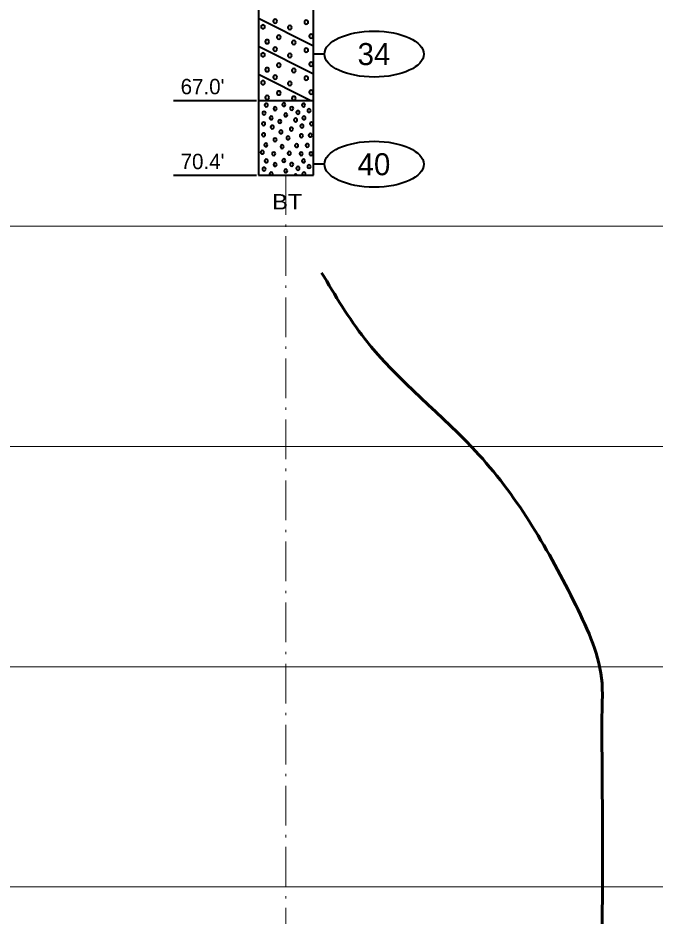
# Model space of a CAD drawing. Extents: x -76 to 974, y -1080 to -735.
# Drawn here: x 746.57 to 775.52, y -1033.41 to -992.64 of the extents above; entities that cross this region are included whole.
import ezdxf
from ezdxf.enums import TextEntityAlignment as Align

# ---------------------------------------------------------------- set-up
doc = ezdxf.new("R2010")
doc.units = 0
doc.header["$LTSCALE"] = 0.36
doc.linetypes.add('DOT_DASHED', pattern=[7.7, 5, -1.2, 0.3, -1.2])
doc.layers.add('27', color=7, linetype='Continuous', lineweight=40)
doc.layers.add('7', color=7, linetype='Continuous', lineweight=13)

msp = doc.modelspace()

# ---------------------------------------------------------------- linework, layer by layer
at = {"layer": '27'}
for p, q in [((757.4958, -991.3789), (757.4958, -996.3789)), ((759.9958, -996.3789), (759.9958, -991.3789)), ((757.4958, -992.6489), (759.9958, -993.8989)), ((757.4958, -993.9189), (759.9958, -995.1689)), ((760.4958, -994.2789), (759.9958, -994.2789)), ((757.4958, -995.1889), (759.8758, -996.3789)), ((753.6395, -996.3789), (757.4069, -996.3789)), ((757.4958, -996.3789), (759.9958, -996.3789)), ((757.4958, -996.3789), (757.4958, -999.7789)), ((759.9958, -999.7789), (759.9958, -996.3789)), ((760.4958, -999.2789), (759.9958, -999.2789)), ((753.6395, -999.7789), (757.4069, -999.7789)), ((757.4958, -999.7789), (759.9958, -999.7789))]:
    msp.add_line(p, q, dxfattribs=at)
for points in [[(758.3464, -992.7841), (758.3345, -992.7396), (758.3019, -992.7071), (758.2575, -992.6952), (758.213, -992.7071), (758.1805, -992.7396), (758.1686, -992.7841), (758.1805, -992.8285), (758.213, -992.861), (758.2575, -992.873), (758.3019, -992.861), (758.3345, -992.8285)], [(759.7613, -992.8349), (759.7494, -992.7905), (759.7168, -992.7579), (759.6724, -992.746), (759.6279, -992.7579), (759.5954, -992.7905), (759.5835, -992.8349), (759.5954, -992.8794), (759.6279, -992.9119), (759.6724, -992.9238), (759.7168, -992.9119), (759.7494, -992.8794)], [(757.7934, -993.0358), (757.7815, -992.9913), (757.7489, -992.9588), (757.7045, -992.9469), (757.66, -992.9588), (757.6275, -992.9913), (757.6156, -993.0358), (757.6275, -993.0802), (757.66, -993.1128), (757.7045, -993.1247), (757.7489, -993.1128), (757.7815, -993.0802)], [(759.0087, -993.0688), (758.9968, -993.0244), (758.9643, -992.9918), (758.9198, -992.9799), (758.8754, -992.9918), (758.8428, -993.0244), (758.8309, -993.0688), (758.8428, -993.1133), (758.8754, -993.1458), (758.9198, -993.1577), (758.9643, -993.1458), (758.9968, -993.1133)], [(758.5129, -993.5061), (758.501, -993.4617), (758.4685, -993.4291), (758.424, -993.4172), (758.3796, -993.4291), (758.347, -993.4617), (758.3351, -993.5061), (758.347, -993.5506), (758.3796, -993.5831), (758.424, -993.595), (758.4685, -993.5831), (758.501, -993.5506)], [(759.9876, -993.4629), (759.9757, -993.4185), (759.9431, -993.3859), (759.8987, -993.374), (759.8542, -993.3859), (759.8217, -993.4185), (759.8098, -993.4629), (759.8217, -993.5074), (759.8542, -993.5399), (759.8987, -993.5518), (759.9431, -993.5399), (759.9757, -993.5074)], [(757.9777, -993.7146), (757.9658, -993.6702), (757.9333, -993.6376), (757.8888, -993.6257), (757.8444, -993.6376), (757.8118, -993.6702), (757.7999, -993.7146), (757.8118, -993.7591), (757.8444, -993.7916), (757.8888, -993.8035), (757.9333, -993.7916), (757.9658, -993.7591)], [(758.3465, -994.0552), (758.3345, -994.0108), (758.302, -993.9783), (758.2576, -993.9663), (758.2131, -993.9783), (758.1806, -994.0108), (758.1687, -994.0552), (758.1806, -994.0997), (758.2131, -994.1322), (758.2576, -994.1441), (758.302, -994.1322), (758.3345, -994.0997)], [(759.1905, -993.7477), (759.1786, -993.7032), (759.146, -993.6707), (759.1016, -993.6588), (759.0571, -993.6707), (759.0246, -993.7032), (759.0127, -993.7477), (759.0246, -993.7921), (759.0571, -993.8247), (759.1016, -993.8366), (759.146, -993.8247), (759.1786, -993.7921)], [(757.7934, -994.307), (757.7815, -994.2626), (757.7489, -994.23), (757.7045, -994.2181), (757.66, -994.23), (757.6275, -994.2626), (757.6156, -994.307), (757.6275, -994.3515), (757.66, -994.384), (757.7045, -994.3959), (757.7489, -994.384), (757.7815, -994.3515)], [(759.0087, -994.3401), (758.9968, -994.2956), (758.9643, -994.2631), (758.9198, -994.2512), (758.8754, -994.2631), (758.8428, -994.2956), (758.8309, -994.3401), (758.8428, -994.3845), (758.8754, -994.4171), (758.9198, -994.429), (758.9643, -994.4171), (758.9968, -994.3845)], [(759.7613, -994.1062), (759.7494, -994.0617), (759.7168, -994.0292), (759.6724, -994.0173), (759.6279, -994.0292), (759.5954, -994.0617), (759.5835, -994.1062), (759.5954, -994.1506), (759.6279, -994.1832), (759.6724, -994.1951), (759.7168, -994.1832), (759.7494, -994.1506)], [(758.5129, -994.7774), (758.501, -994.733), (758.4685, -994.7004), (758.424, -994.6885), (758.3796, -994.7004), (758.347, -994.733), (758.3351, -994.7774), (758.347, -994.8219), (758.3796, -994.8544), (758.424, -994.8663), (758.4685, -994.8544), (758.501, -994.8219)], [(759.9876, -994.7342), (759.9757, -994.6897), (759.9431, -994.6572), (759.8987, -994.6453), (759.8542, -994.6572), (759.8217, -994.6897), (759.8098, -994.7342), (759.8217, -994.7786), (759.8542, -994.8112), (759.8987, -994.8231), (759.9431, -994.8112), (759.9757, -994.7786)], [(757.9777, -994.9859), (757.9658, -994.9414), (757.9333, -994.9089), (757.8888, -994.897), (757.8444, -994.9089), (757.8118, -994.9414), (757.7999, -994.9859), (757.8118, -995.0303), (757.8444, -995.0629), (757.8888, -995.0748), (757.9333, -995.0629), (757.9658, -995.0303)], [(759.1905, -995.0189), (759.1786, -994.9745), (759.146, -994.942), (759.1016, -994.93), (759.0571, -994.942), (759.0246, -994.9745), (759.0127, -995.0189), (759.0246, -995.0634), (759.0571, -995.0959), (759.1016, -995.1078), (759.146, -995.0959), (759.1786, -995.0634)], [(757.7934, -995.5758), (757.7815, -995.5313), (757.7489, -995.4988), (757.7045, -995.4869), (757.66, -995.4988), (757.6275, -995.5313), (757.6156, -995.5758), (757.6275, -995.6202), (757.66, -995.6528), (757.7045, -995.6647), (757.7489, -995.6528), (757.7815, -995.6202)], [(758.3464, -995.3241), (758.3345, -995.2796), (758.3019, -995.2471), (758.2575, -995.2352), (758.213, -995.2471), (758.1805, -995.2796), (758.1686, -995.3241), (758.1805, -995.3685), (758.213, -995.401), (758.2575, -995.413), (758.3019, -995.401), (758.3345, -995.3685)], [(759.0087, -995.6088), (758.9968, -995.5644), (758.9643, -995.5318), (758.9198, -995.5199), (758.8754, -995.5318), (758.8428, -995.5644), (758.8309, -995.6088), (758.8428, -995.6533), (758.8754, -995.6858), (758.9198, -995.6977), (758.9643, -995.6858), (758.9968, -995.6533)], [(759.7613, -995.3749), (759.7494, -995.3305), (759.7168, -995.2979), (759.6724, -995.286), (759.6279, -995.2979), (759.5954, -995.3305), (759.5835, -995.3749), (759.5954, -995.4194), (759.6279, -995.4519), (759.6724, -995.4638), (759.7168, -995.4519), (759.7494, -995.4194)], [(758.5129, -996.0461), (758.501, -996.0017), (758.4685, -995.9691), (758.424, -995.9572), (758.3796, -995.9691), (758.347, -996.0017), (758.3351, -996.0461), (758.347, -996.0906), (758.3796, -996.1231), (758.424, -996.135), (758.4685, -996.1231), (758.501, -996.0906)], [(759.9876, -996.0029), (759.9757, -995.9585), (759.9431, -995.9259), (759.8987, -995.914), (759.8542, -995.9259), (759.8217, -995.9585), (759.8098, -996.0029), (759.8217, -996.0474), (759.8542, -996.0799), (759.8987, -996.0918), (759.9431, -996.0799), (759.9757, -996.0474)], [(757.9777, -996.2546), (757.9658, -996.2102), (757.9333, -996.1776), (757.8888, -996.1657), (757.8444, -996.1776), (757.8118, -996.2102), (757.7999, -996.2546), (757.8118, -996.2991), (757.8444, -996.3316), (757.8888, -996.3435), (757.9333, -996.3316), (757.9658, -996.2991)], [(759.1905, -996.2877), (759.1786, -996.2432), (759.146, -996.2107), (759.1016, -996.1988), (759.0571, -996.2107), (759.0246, -996.2432), (759.0127, -996.2877), (759.0246, -996.3321), (759.0571, -996.3647), (759.1016, -996.3766), (759.146, -996.3647), (759.1786, -996.3321)], [(757.9277, -996.5916), (757.9175, -996.5535), (757.8896, -996.5256), (757.8515, -996.5154), (757.8134, -996.5256), (757.7855, -996.5535), (757.7753, -996.5916), (757.7855, -996.6297), (757.8134, -996.6575), (757.8515, -996.6678), (757.8896, -996.6575), (757.9175, -996.6297)], [(758.3326, -996.7568), (758.3224, -996.7187), (758.2945, -996.6908), (758.2564, -996.6806), (758.2183, -996.6908), (758.1904, -996.7187), (758.1802, -996.7568), (758.1904, -996.7949), (758.2183, -996.8228), (758.2564, -996.833), (758.2945, -996.8228), (758.3224, -996.7949)], [(758.7287, -996.572), (758.7184, -996.5339), (758.6906, -996.506), (758.6525, -996.4958), (758.6144, -996.506), (758.5865, -996.5339), (758.5763, -996.572), (758.5865, -996.6101), (758.6144, -996.638), (758.6525, -996.6482), (758.6906, -996.638), (758.7184, -996.6101)], [(759.0877, -996.7478), (759.0775, -996.7097), (759.0496, -996.6818), (759.0115, -996.6716), (758.9734, -996.6818), (758.9455, -996.7097), (758.9353, -996.7478), (758.9455, -996.7859), (758.9734, -996.8138), (759.0115, -996.824), (759.0496, -996.8138), (759.0775, -996.7859)], [(759.3659, -996.9251), (759.3557, -996.887), (759.3278, -996.8591), (759.2897, -996.8489), (759.2516, -996.8591), (759.2237, -996.887), (759.2135, -996.9251), (759.2237, -996.9632), (759.2516, -996.9911), (759.2897, -997.0013), (759.3278, -996.9911), (759.3557, -996.9632)], [(759.6223, -996.5916), (759.6121, -996.5535), (759.5842, -996.5256), (759.5461, -996.5154), (759.508, -996.5256), (759.4801, -996.5535), (759.4699, -996.5916), (759.4801, -996.6297), (759.508, -996.6576), (759.5461, -996.6678), (759.5842, -996.6576), (759.6121, -996.6297)], [(759.8732, -996.8437), (759.863, -996.8056), (759.8351, -996.7777), (759.797, -996.7675), (759.7589, -996.7777), (759.731, -996.8056), (759.7208, -996.8437), (759.731, -996.8818), (759.7589, -996.9097), (759.797, -996.9199), (759.8351, -996.9097), (759.863, -996.8818)], [(757.8315, -996.9594), (757.8213, -996.9213), (757.7934, -996.8934), (757.7553, -996.8832), (757.7172, -996.8934), (757.6893, -996.9213), (757.6791, -996.9594), (757.6893, -996.9975), (757.7172, -997.0254), (757.7553, -997.0356), (757.7934, -997.0254), (757.8213, -996.9975)], [(758.1544, -997.1781), (758.1442, -997.14), (758.1163, -997.1121), (758.0782, -997.1019), (758.0401, -997.1121), (758.0122, -997.14), (758.002, -997.1781), (758.0122, -997.2162), (758.0401, -997.2441), (758.0782, -997.2543), (758.1163, -997.2441), (758.1442, -997.2162)], [(758.546, -997.3395), (758.5358, -997.3014), (758.5079, -997.2735), (758.4698, -997.2633), (758.4317, -997.2735), (758.4038, -997.3014), (758.3936, -997.3395), (758.4038, -997.3776), (758.4317, -997.4055), (758.4698, -997.4157), (758.5079, -997.4055), (758.5358, -997.3776)], [(758.8176, -997.0426), (758.8074, -997.0045), (758.7795, -996.9766), (758.7414, -996.9664), (758.7033, -996.9766), (758.6754, -997.0045), (758.6652, -997.0426), (758.6754, -997.0807), (758.7033, -997.1086), (758.7414, -997.1188), (758.7795, -997.1086), (758.8074, -997.0807)], [(759.2617, -997.2709), (759.2515, -997.2328), (759.2236, -997.2049), (759.1855, -997.1947), (759.1474, -997.2049), (759.1195, -997.2328), (759.1093, -997.2709), (759.1195, -997.309), (759.1474, -997.3369), (759.1855, -997.3471), (759.2236, -997.3369), (759.2515, -997.309)], [(759.6431, -997.1781), (759.6329, -997.14), (759.605, -997.1121), (759.5669, -997.1019), (759.5288, -997.1121), (759.5009, -997.14), (759.4907, -997.1781), (759.5009, -997.2162), (759.5288, -997.2441), (759.5669, -997.2543), (759.605, -997.2441), (759.6329, -997.2162)], [(757.8086, -997.4438), (757.7984, -997.4057), (757.7705, -997.3778), (757.7324, -997.3676), (757.6943, -997.3778), (757.6664, -997.4057), (757.6562, -997.4438), (757.6664, -997.4819), (757.6943, -997.5097), (757.7324, -997.52), (757.7705, -997.5097), (757.7984, -997.4819)], [(758.2002, -997.5938), (758.19, -997.5557), (758.1621, -997.5278), (758.124, -997.5176), (758.0859, -997.5278), (758.058, -997.5557), (758.0478, -997.5938), (758.058, -997.6319), (758.0859, -997.6598), (758.124, -997.67), (758.1621, -997.6598), (758.19, -997.6319)], [(759.0723, -997.6815), (759.0621, -997.6434), (759.0342, -997.6155), (758.9961, -997.6053), (758.958, -997.6155), (758.9301, -997.6434), (758.9199, -997.6815), (758.9301, -997.7196), (758.958, -997.7475), (758.9961, -997.7577), (759.0342, -997.7475), (759.0621, -997.7196)], [(759.5503, -997.548), (759.5401, -997.5099), (759.5122, -997.482), (759.4741, -997.4718), (759.436, -997.482), (759.4081, -997.5099), (759.3979, -997.548), (759.4081, -997.5861), (759.436, -997.614), (759.4741, -997.6242), (759.5122, -997.614), (759.5401, -997.5861)], [(759.9889, -997.4438), (759.9786, -997.4057), (759.9508, -997.3778), (759.9127, -997.3676), (759.8746, -997.3778), (759.8467, -997.4057), (759.8365, -997.4438), (759.8467, -997.4819), (759.8746, -997.5097), (759.9127, -997.52), (759.9508, -997.5097), (759.9786, -997.4819)], [(757.8086, -997.9396), (757.7984, -997.9015), (757.7705, -997.8736), (757.7324, -997.8634), (757.6943, -997.8736), (757.6664, -997.9015), (757.6562, -997.9396), (757.6664, -997.9777), (757.6943, -998.0055), (757.7324, -998.0158), (757.7705, -998.0055), (757.7984, -997.9777)], [(758.5943, -997.8124), (758.5841, -997.7743), (758.5562, -997.7464), (758.5181, -997.7362), (758.48, -997.7464), (758.4521, -997.7743), (758.4419, -997.8124), (758.4521, -997.8505), (758.48, -997.8784), (758.5181, -997.8886), (758.5562, -997.8784), (758.5841, -997.8505)], [(758.9223, -998.087), (758.912, -998.0489), (758.8842, -998.021), (758.8461, -998.0108), (758.808, -998.021), (758.7801, -998.0489), (758.7699, -998.087), (758.7801, -998.1251), (758.808, -998.153), (758.8461, -998.1632), (758.8842, -998.153), (758.912, -998.1251)], [(759.5274, -997.9866), (759.5172, -997.9485), (759.4893, -997.9206), (759.4512, -997.9104), (759.4131, -997.9206), (759.3852, -997.9485), (759.375, -997.9866), (759.3852, -998.0247), (759.4131, -998.0526), (759.4512, -998.0628), (759.4893, -998.0526), (759.5172, -998.0247)], [(759.9316, -997.9624), (759.9214, -997.9243), (759.8935, -997.8964), (759.8554, -997.8862), (759.8173, -997.8964), (759.7895, -997.9243), (759.7792, -997.9624), (759.7895, -998.0005), (759.8173, -998.0284), (759.8554, -998.0386), (759.8935, -998.0284), (759.9214, -998.0005)], [(757.9116, -998.4023), (757.9014, -998.3642), (757.8735, -998.3363), (757.8354, -998.3261), (757.7973, -998.3363), (757.7694, -998.3642), (757.7592, -998.4023), (757.7694, -998.4404), (757.7973, -998.4683), (757.8354, -998.4785), (757.8735, -998.4683), (757.9014, -998.4404)], [(758.3273, -998.1709), (758.3171, -998.1328), (758.2892, -998.1049), (758.2511, -998.0947), (758.213, -998.1049), (758.1851, -998.1328), (758.1749, -998.1709), (758.1851, -998.209), (758.213, -998.2369), (758.2511, -998.2471), (758.2892, -998.2369), (758.3171, -998.209)], [(758.6502, -998.4824), (758.64, -998.4443), (758.6121, -998.4164), (758.574, -998.4062), (758.5359, -998.4164), (758.508, -998.4443), (758.4978, -998.4824), (758.508, -998.5205), (758.5359, -998.5484), (758.574, -998.5586), (758.6121, -998.5484), (758.64, -998.5205)], [(759.3075, -998.4315), (759.2972, -998.3934), (759.2694, -998.3655), (759.2313, -998.3553), (759.1932, -998.3655), (759.1653, -998.3934), (759.1551, -998.4315), (759.1653, -998.4696), (759.1932, -998.4975), (759.2313, -998.5077), (759.2694, -998.4975), (759.2972, -998.4696)], [(759.7931, -998.4239), (759.7829, -998.3858), (759.755, -998.3579), (759.7169, -998.3477), (759.6788, -998.3579), (759.6509, -998.3858), (759.6407, -998.4239), (759.6509, -998.462), (759.6788, -998.4899), (759.7169, -998.5001), (759.755, -998.4899), (759.7829, -998.462)], [(757.7501, -998.7354), (757.7399, -998.6973), (757.712, -998.6694), (757.6739, -998.6592), (757.6358, -998.6694), (757.608, -998.6973), (757.5977, -998.7354), (757.608, -998.7735), (757.6358, -998.8014), (757.6739, -998.8116), (757.712, -998.8014), (757.7399, -998.7735)], [(758.2688, -998.8053), (758.2586, -998.7672), (758.2307, -998.7393), (758.1926, -998.7291), (758.1545, -998.7393), (758.1266, -998.7672), (758.1164, -998.8053), (758.1266, -998.8434), (758.1545, -998.8713), (758.1926, -998.8815), (758.2307, -998.8713), (758.2586, -998.8434)], [(758.9731, -998.7824), (758.9629, -998.7443), (758.935, -998.7164), (758.8969, -998.7062), (758.8588, -998.7164), (758.8309, -998.7443), (758.8207, -998.7824), (758.8309, -998.8205), (758.8588, -998.8484), (758.8969, -998.8586), (758.935, -998.8484), (758.9629, -998.8205)], [(759.5159, -998.8053), (759.5057, -998.7672), (759.4778, -998.7393), (759.4397, -998.7291), (759.4016, -998.7393), (759.3738, -998.7672), (759.3635, -998.8053), (759.3738, -998.8434), (759.4016, -998.8713), (759.4397, -998.8815), (759.4778, -998.8713), (759.5057, -998.8434)], [(759.966, -998.8053), (759.9558, -998.7672), (759.9279, -998.7393), (759.8898, -998.7291), (759.8517, -998.7393), (759.8238, -998.7672), (759.8136, -998.8053), (759.8238, -998.8434), (759.8517, -998.8713), (759.8898, -998.8815), (759.9279, -998.8713), (759.9558, -998.8434)], [(757.9277, -999.1316), (757.9175, -999.0935), (757.8896, -999.0656), (757.8515, -999.0554), (757.8134, -999.0656), (757.7855, -999.0935), (757.7753, -999.1316), (757.7855, -999.1697), (757.8134, -999.1975), (757.8515, -999.2078), (757.8896, -999.1975), (757.9175, -999.1697)], [(758.3326, -999.2968), (758.3224, -999.2587), (758.2945, -999.2308), (758.2564, -999.2206), (758.2183, -999.2308), (758.1904, -999.2587), (758.1802, -999.2968), (758.1904, -999.3349), (758.2183, -999.3628), (758.2564, -999.373), (758.2945, -999.3628), (758.3224, -999.3349)], [(758.7287, -999.112), (758.7184, -999.0739), (758.6906, -999.046), (758.6525, -999.0358), (758.6144, -999.046), (758.5865, -999.0739), (758.5763, -999.112), (758.5865, -999.1501), (758.6144, -999.178), (758.6525, -999.1882), (758.6906, -999.178), (758.7184, -999.1501)], [(759.0877, -999.2878), (759.0775, -999.2497), (759.0496, -999.2218), (759.0115, -999.2116), (758.9734, -999.2218), (758.9455, -999.2497), (758.9353, -999.2878), (758.9455, -999.3259), (758.9734, -999.3538), (759.0115, -999.364), (759.0496, -999.3538), (759.0775, -999.3259)], [(759.6223, -999.1316), (759.6121, -999.0935), (759.5842, -999.0656), (759.5461, -999.0554), (759.508, -999.0656), (759.4801, -999.0935), (759.4699, -999.1316), (759.4801, -999.1697), (759.508, -999.1976), (759.5461, -999.2078), (759.5842, -999.1976), (759.6121, -999.1697)], [(757.8315, -999.4994), (757.8213, -999.4613), (757.7934, -999.4334), (757.7553, -999.4232), (757.7172, -999.4334), (757.6893, -999.4613), (757.6791, -999.4994), (757.6893, -999.5375), (757.7172, -999.5654), (757.7553, -999.5756), (757.7934, -999.5654), (757.8213, -999.5375)], [(758.1442, -999.7562), (758.1544, -999.7181), (758.1442, -999.68), (758.1163, -999.6521), (758.0782, -999.6419), (758.0401, -999.6521), (758.0122, -999.68), (758.002, -999.7181), (758.0122, -999.7562), (758.035, -999.7789), (758.1214, -999.7789)], [(758.8176, -999.5826), (758.8074, -999.5445), (758.7795, -999.5166), (758.7414, -999.5064), (758.7033, -999.5166), (758.6754, -999.5445), (758.6652, -999.5826), (758.6754, -999.6207), (758.7033, -999.6486), (758.7414, -999.6588), (758.7795, -999.6486), (758.8074, -999.6207)], [(759.3659, -999.4651), (759.3557, -999.427), (759.3278, -999.3991), (759.2897, -999.3889), (759.2516, -999.3991), (759.2237, -999.427), (759.2135, -999.4651), (759.2237, -999.5032), (759.2516, -999.5311), (759.2897, -999.5413), (759.3278, -999.5311), (759.3557, -999.5032)], [(759.6329, -999.7562), (759.6431, -999.7181), (759.6329, -999.68), (759.605, -999.6521), (759.5669, -999.6419), (759.5288, -999.6521), (759.5009, -999.68), (759.4907, -999.7181), (759.5009, -999.7562), (759.5236, -999.7789), (759.6101, -999.7789)], [(759.8732, -999.3837), (759.863, -999.3456), (759.8351, -999.3177), (759.797, -999.3075), (759.7589, -999.3177), (759.731, -999.3456), (759.7208, -999.3837), (759.731, -999.4218), (759.7589, -999.4497), (759.797, -999.4599), (759.8351, -999.4497), (759.863, -999.4218)], [(759.2515, -999.7728), (759.2236, -999.7449), (759.1855, -999.7347), (759.1474, -999.7449), (759.1195, -999.7728), (759.1178, -999.7789), (759.2531, -999.7789)]]:
    msp.add_lwpolyline(points, close=True, dxfattribs=at)
for centre in [(762.7532, -994.2789), (762.7532, -999.2789)]:
    msp.add_ellipse(centre, major_axis=(2.2574, 0), ratio=0.461538, dxfattribs=at)
at = {"layer": '27', "lineweight": 60}
msp.add_spline([(760.3688, -1004.2028), (762.3318, -1007.2079), (767.5162, -1012.4706), (771.9154, -1019.2999), (773.106, -1022.8358), (773.106, -1024.0901), (773.106, -1026.0889), (773.0872, -1037.8641)], degree=3, dxfattribs=at)
at = {"layer": '7', "linetype": 'DOT_DASHED'}
msp.add_line((758.7457, -999.7789), (758.7457, -1039.8524), dxfattribs=at)
at = {"layer": '7'}
for p, q in [((726.8972, -1002.09), (818.1909, -1002.09)), ((734.1382, -1012.09), (818.1909, -1012.09)), ((734.0477, -1022.09), (818.1909, -1022.09)), ((734.1382, -1032.09), (818.1909, -1032.09))]:
    msp.add_line(p, q, dxfattribs=at)

# ---------------------------------------------------------------- texts
at = {"layer": '27'}
for s, p in [('34', (762.7458, -994.7788)), ('40', (762.7459, -999.7788))]:
    msp.add_text(s, height=1, dxfattribs=at).set_placement(p, align=Align.CENTER)
for s, p in [("67.0'", (753.9635, -996.1025)), ("70.4'", (753.9635, -999.5025))]:
    msp.add_text(s, height=0.6976, dxfattribs=at).set_placement(p)
at = {"layer": '27', "width": 1.15}
msp.add_text('BT', height=0.6976, dxfattribs=at).set_placement((758.8073, -1001.3323), align=Align.CENTER)

doc.saveas('drawing.dxf')
